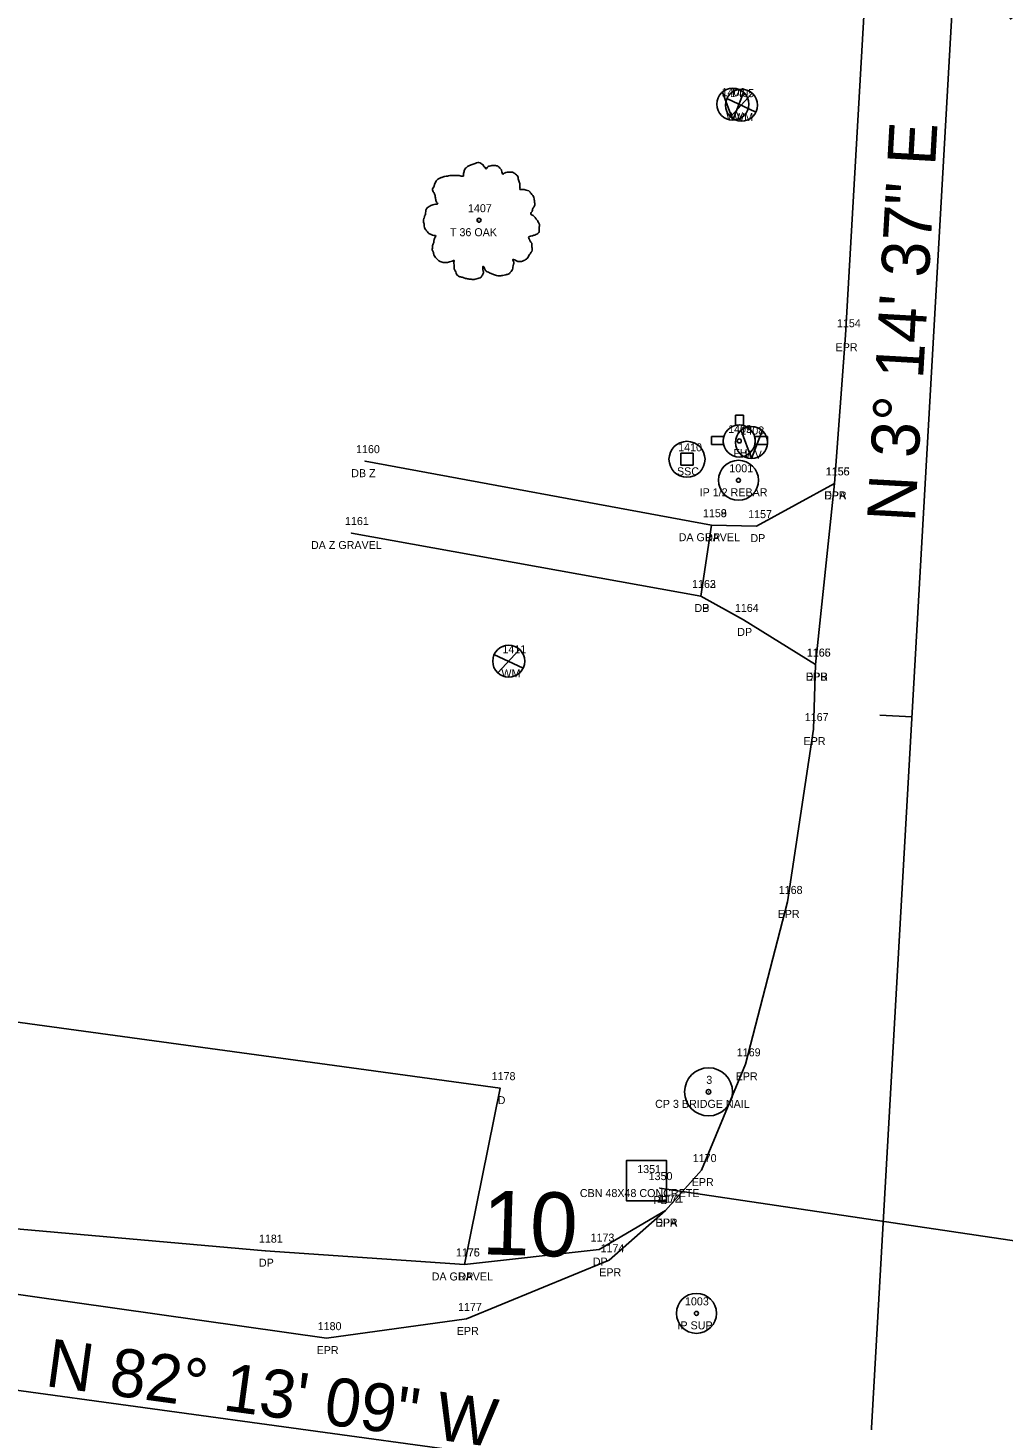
# Model space of a CAD drawing. Extents: x 1812340 to 1815011, y 1177659 to 1180159.
# Drawn here: x 1813558.8 to 1813680.6, y 1178765.1 to 1178939 of the extents above; entities that cross this region are included whole.
import ezdxf

# ---------------------------------------------------------------- set-up
doc = ezdxf.new("R2010")
doc.units = 0
for name, color, linetype in [('RD_EX_DR_Inlet', 7, 'Continuous'), ('RD_EX_DR_Inlet_txCode', 7, 'Continuous'), ('RD_EX_DR_Pipe', 7, 'Continuous'), ('RD_EX_DR_Pipe_txCode', 7, 'Continuous'), ('RD_EX_Driveway', 7, 'Continuous'), ('RD_EX_Driveway_txCode', 7, 'Continuous'), ('RD_EX_DV_Prop_txCode', 7, 'Continuous'), ('RD_EX_DV_PropPin', 7, 'Continuous'), ('RD_EX_Road', 7, 'Continuous'), ('RD_EX_Road_txCode', 7, 'Continuous'), ('RD_EX_UT', 7, 'Continuous'), ('RD_EX_UT_txCode', 7, 'Continuous'), ('RD_EX_VEG', 7, 'Continuous'), ('RD_EX_VEG_txCode', 7, 'Continuous'), ('RD_HC_CL', 7, 'Continuous'), ('RD_HC_Data', 7, 'Continuous'), ('RD_HC_Data_Tic', 7, 'Continuous'), ('RD_HC_TX_Sta50', 7, 'Continuous'), ('RD_HC_txCode', 7, 'Continuous'), ('RD_SMD_Locator', 7, 'Continuous')]:
    doc.layers.add(name, color=color, linetype=linetype)

msp = doc.modelspace()

# ---------------------------------------------------------------- linework, layer by layer
at = {"layer": 'RD_EX_DR_Inlet'}
msp.add_line((1813638.56, 1178792.49), (1813638.56, 1178797.49), dxfattribs=at)
msp.add_lwpolyline([(1813638.56, 1178792.49), (1813638.56, 1178797.49), (1813633.56, 1178797.49), (1813633.56, 1178792.49)], close=True, dxfattribs=at)
at = {"layer": 'RD_EX_DR_Pipe'}
msp.add_line((1813690.77, 1178786.15), (1813637.71, 1178794.06), dxfattribs=at)
at = {"layer": 'RD_EX_Driveway'}
for p, q in [((1813644.18, 1178876.9), (1813600.91, 1178884.9)), ((1813599.2, 1178875.92), (1813642.83, 1178868.05))]:
    msp.add_line(p, q, dxfattribs=at)
for points in [[(1813659.53, 1178882.12), (1813649.82, 1178876.78), (1813644.18, 1178876.9), (1813642.83, 1178868.05), (1813648.18, 1178865.06), (1813657.19, 1178859.48)], [(1813613.34, 1178784.52), (1813617.78, 1178806.55), (1813543.17, 1178816.74), (1813525.31, 1178791.79)], [(1813638.42, 1178791.25), (1813630.13, 1178786.38), (1813613.34, 1178784.52), (1813588.43, 1178786.24), (1813525.31, 1178791.79), (1813522.62, 1178785.74)]]:
    msp.add_lwpolyline(points, dxfattribs=at)
at = {"layer": 'RD_EX_DV_PropPin'}
for centre, radius in [((1813647.55, 1178882.51), 2.5), ((1813647.55, 1178882.51), 0.25), ((1813642.3, 1178778.41), 2.5), ((1813642.3, 1178778.41), 0.25)]:
    msp.add_circle(centre, radius, dxfattribs=at)
at = {"layer": 'RD_EX_Road'}
msp.add_lwpolyline([(1813668.47, 1179045.78), (1813666.19, 1178996.77), (1813663.63, 1178947.81), (1813660.91, 1178900.64), (1813659.53, 1178882.12), (1813657.19, 1178859.48), (1813656.91, 1178851.42), (1813653.67, 1178829.82), (1813648.43, 1178809.53), (1813642.94, 1178796.31), (1813638.42, 1178791.25), (1813631.39, 1178785.04), (1813613.59, 1178777.71), (1813596.09, 1178775.31), (1813522.62, 1178785.74), (1813518.21, 1178785.19), (1813499.47, 1178787.87), (1813450.56, 1178796.06), (1813414.35, 1178802.92), (1813398.64, 1178806.42), (1813355.44, 1178817.13)], dxfattribs=at)
at = {"layer": 'RD_EX_UT'}
for p, q in [((1813646.85, 1178927.52), (1813645.55, 1178931)), ((1813646.56, 1178927.93), (1813649.23, 1178930.83)), ((1813646.85, 1178927.52), (1813648.18, 1178930.96)), ((1813646.08, 1178930.23), (1813649.71, 1178928.51)), ((1813647.19, 1178890.64), (1813647.19, 1178889.37)), ((1813648.19, 1178890.64), (1813647.19, 1178890.64)), ((1813648.19, 1178889.34), (1813648.19, 1178890.64)), ((1813649.18, 1178885.24), (1813647.88, 1178888.72)), ((1813649.18, 1178885.24), (1813650.5, 1178888.68)), ((1813645.73, 1178887.99), (1813644.17, 1178887.99)), ((1813644.17, 1178887.99), (1813644.17, 1178886.99)), ((1813644.17, 1178886.99), (1813645.69, 1178886.99)), ((1813651.17, 1178887.99), (1813649.56, 1178887.99)), ((1813649.6, 1178886.99), (1813651.17, 1178886.99)), ((1813651.17, 1178886.99), (1813651.17, 1178887.99)), ((1813641.87, 1178885.88), (1813640.37, 1178885.88)), ((1813640.37, 1178885.88), (1813640.37, 1178884.38)), ((1813641.87, 1178884.38), (1813641.87, 1178885.88)), ((1813640.37, 1178884.38), (1813641.87, 1178884.38)), ((1813617.5, 1178858.44), (1813620.16, 1178861.34)), ((1813617.01, 1178860.74), (1813620.65, 1178859.02))]:
    msp.add_line(p, q, dxfattribs=at)
for centre, radius in [((1813646.85, 1178929.51), 2), ((1813647.92, 1178929.39), 2), ((1813647.65, 1178887.42), 2), ((1813649.18, 1178887.23), 2), ((1813641.12, 1178885.13), 2.25), ((1813647.65, 1178887.42), 0.25), ((1813618.85, 1178859.9), 2)]:
    msp.add_circle(centre, radius, dxfattribs=at)
for start, end in [(74.2455, 103.2128), (163.3387, 192.315), (347.685, 16.6613)]:
    msp.add_arc((1813647.65, 1178887.42), 2, start, end, dxfattribs=at)
at = {"layer": 'RD_EX_VEG'}
for centre, radius in [((1813615.14, 1178915.01), 0.25), ((1813615.13, 1178914.99), 0.0001)]:
    msp.add_circle(centre, radius, dxfattribs=at)
for points in [[(1813615.28, 1178922.18), (1813614.98, 1178922.21), (1813614.65, 1178922.11), (1813614.4, 1178922.01), (1813614.18, 1178921.93), (1813613.95, 1178921.83), (1813613.65, 1178921.66), (1813613.43, 1178921.46), (1813613.3, 1178921.21), (1813613.25, 1178920.98), (1813613.2, 1178920.71), (1813613.2, 1178920.53), (1813613.08, 1178920.51), (1813612.93, 1178920.53), (1813612.68, 1178920.61), (1813612.43, 1178920.61), (1813612.18, 1178920.61), (1813611.83, 1178920.58), (1813611.48, 1178920.58), (1813611.2, 1178920.53), (1813610.88, 1178920.48), (1813610.5, 1178920.36), (1813610.15, 1178920.23), (1813609.85, 1178919.98), (1813609.6, 1178919.51), (1813609.48, 1178919.16), (1813609.33, 1178918.91), (1813609.48, 1178918.46), (1813609.65, 1178918.11), (1813609.68, 1178917.91), (1813609.75, 1178917.48), (1813609.85, 1178917.26), (1813609.98, 1178917.06), (1813609.9, 1178917.03), (1813609.53, 1178916.98), (1813609.23, 1178916.88), (1813608.8, 1178916.66), (1813608.58, 1178916.43), (1813608.48, 1178916.11), (1813608.45, 1178915.76), (1813608.35, 1178915.56), (1813608.28, 1178915.28), (1813608.25, 1178915.21), (1813608.2, 1178914.88), (1813608.3, 1178914.43), (1813608.33, 1178914.08), (1813608.45, 1178913.86), (1813608.6, 1178913.68), (1813608.78, 1178913.43), (1813609.18, 1178913.21), (1813609.5, 1178913.11), (1813609.7, 1178913.09), (1813609.53, 1178912.59), (1813609.48, 1178912.24), (1813609.35, 1178911.84), (1813609.35, 1178911.76), (1813609.3, 1178911.29), (1813609.45, 1178910.96), (1813609.53, 1178910.59), (1813609.7, 1178910.36), (1813609.98, 1178910.06), (1813610.3, 1178909.84), (1813610.8, 1178909.71), (1813611.2, 1178909.74), (1813611.78, 1178909.91), (1813612.03, 1178909.99), (1813612, 1178909.81), (1813612.03, 1178909.44), (1813612.03, 1178909.01), (1813612.18, 1178908.69), (1813612.28, 1178908.41), (1813612.43, 1178908.16), (1813612.75, 1178907.94), (1813613.15, 1178907.86), (1813613.58, 1178907.71), (1813614.03, 1178907.64), (1813614.53, 1178907.61), (1813615.13, 1178907.76), (1813615.4, 1178907.89), (1813615.5, 1178908.06), (1813615.7, 1178908.44), (1813615.65, 1178908.66), (1813615.68, 1178909.26), (1813615.78, 1178909.09), (1813615.95, 1178908.74), (1813616.45, 1178908.44), (1813616.85, 1178908.26), (1813617.33, 1178908.11), (1813617.63, 1178908.04), (1813618.1, 1178908.11), (1813618.48, 1178908.19), (1813618.85, 1178908.31), (1813619.15, 1178908.59), (1813619.33, 1178908.86), (1813619.38, 1178909.14), (1813619.45, 1178909.51), (1813619.5, 1178909.69)], [(1813619.5, 1178909.69), (1813619.43, 1178909.86), (1813619.38, 1178910.11), (1813619.45, 1178910.09), (1813619.62, 1178910.04), (1813619.9, 1178909.91), (1813620.12, 1178909.84), (1813620.45, 1178909.86), (1813620.72, 1178909.96), (1813621.17, 1178910.24), (1813621.45, 1178910.71), (1813621.72, 1178911.11), (1813621.8, 1178911.44), (1813621.75, 1178911.66), (1813621.72, 1178912.16), (1813621.52, 1178912.41), (1813621.47, 1178912.54), (1813621.37, 1178912.94), (1813621.45, 1178912.99), (1813621.72, 1178913.04), (1813622.1, 1178913.16), (1813622.37, 1178913.28), (1813622.6, 1178913.46), (1813622.67, 1178913.68), (1813622.65, 1178914.08), (1813622.7, 1178914.48), (1813622.62, 1178914.63), (1813622.52, 1178914.78), (1813622.45, 1178914.98), (1813622.3, 1178915.13), (1813622.2, 1178915.28), (1813622.1, 1178915.38), (1813621.97, 1178915.53), (1813621.8, 1178915.66), (1813621.65, 1178915.71), (1813621.6, 1178915.86), (1813621.75, 1178916.06), (1813621.8, 1178916.16), (1813621.82, 1178916.38), (1813622.05, 1178916.73), (1813622.1, 1178917.13), (1813622.05, 1178917.56), (1813622, 1178917.83), (1813621.85, 1178918.11), (1813621.65, 1178918.36), (1813621.52, 1178918.53), (1813621.35, 1178918.66), (1813621.02, 1178918.78), (1813620.77, 1178918.83), (1813620.42, 1178918.83), (1813620.22, 1178918.88), (1813620.25, 1178918.93), (1813620.25, 1178919.08), (1813620.25, 1178919.36), (1813620.17, 1178919.81), (1813620.02, 1178920.31), (1813620.02, 1178920.33), (1813619.92, 1178920.58), (1813619.7, 1178920.78), (1813619.52, 1178920.88), (1813619.33, 1178921.01), (1813619.08, 1178921.03), (1813618.78, 1178921.03), (1813618.5, 1178920.98), (1813618.3, 1178920.88), (1813618.13, 1178920.76), (1813618.05, 1178920.91), (1813617.95, 1178921.21), (1813617.9, 1178921.36), (1813617.75, 1178921.53), (1813617.53, 1178921.73), (1813617.08, 1178921.86), (1813616.45, 1178921.78), (1813616.15, 1178921.58), (1813616, 1178921.41), (1813615.95, 1178921.53), (1813615.75, 1178921.73), (1813615.65, 1178921.91), (1813615.48, 1178922.03), (1813615.33, 1178922.13), (1813615.23, 1178922.18)]]:
    msp.add_spline(points, degree=3, dxfattribs=at)
at = {"layer": 'RD_HC_CL'}
for p, q in [((1813663.56, 1178753.12), (1813680.53, 1179052.64)), ((1813641.28, 1178757.34), (1813538.22, 1178771.42))]:
    msp.add_line(p, q, dxfattribs=at)
at = {"layer": 'RD_HC_Data'}
for radius in [3, 0.282]:
    msp.add_circle((1813643.81, 1178806.09), radius, dxfattribs=at)
at = {"layer": 'RD_HC_Data_Tic'}
msp.add_line((1813669.21, 1178852.96), (1813665.22, 1178853.18), dxfattribs=at)
at = {"layer": 'RD_SMD_Locator'}
for centre in [(1813660.91, 1178900.64), (1813600.91, 1178884.9), (1813659.53, 1178882.12), (1813659.53, 1178882.12), (1813644.18, 1178876.9), (1813644.18, 1178876.9), (1813649.82, 1178876.78), (1813599.2, 1178875.92), (1813642.83, 1178868.05), (1813642.83, 1178868.05), (1813648.18, 1178865.06), (1813657.19, 1178859.48), (1813657.19, 1178859.48), (1813656.91, 1178851.42), (1813653.67, 1178829.82), (1813648.43, 1178809.53), (1813617.78, 1178806.55), (1813643.81, 1178806.09), (1813642.94, 1178796.31), (1813637.71, 1178794.06), (1813638.42, 1178791.25), (1813638.42, 1178791.25), (1813588.43, 1178786.24), (1813630.13, 1178786.38), (1813613.34, 1178784.52), (1813613.34, 1178784.52), (1813631.39, 1178785.04), (1813613.59, 1178777.71), (1813596.09, 1178775.31)]:
    msp.add_circle(centre, 0.001, dxfattribs=at)

# ---------------------------------------------------------------- texts
at = {"layer": 'RD_EX_DR_Inlet_txCode'}
for s, p in [('1351', (1813634.9, 1178795.94)), ('CBN 48X48 CONCRETE', (1813627.74, 1178792.94))]:
    msp.add_text(s, height=1, dxfattribs=at).set_placement(p)
at = {"layer": 'RD_EX_DR_Pipe_txCode'}
for s, p in [('1350', (1813636.33, 1178795.06)), ('PB', (1813636.93, 1178792.06))]:
    msp.add_text(s, height=1, dxfattribs=at).set_placement(p)
at = {"layer": 'RD_EX_Driveway_txCode'}
for s, p in [('1160', (1813599.78, 1178885.9)), ('DB Z', (1813599.18, 1178882.9)), ('1156', (1813658.44, 1178883.12)), ('DPA', (1813658.26, 1178880.12)), ('1158', (1813643.11, 1178877.9)), ('1159', (1813643.11, 1178877.9)), ('1157', (1813648.76, 1178877.78)), ('1161', (1813598.4, 1178876.92)), ('DA Z GRAVEL', (1813594.15, 1178873.92)), ('DA GRAVEL', (1813640.08, 1178874.9)), ('DP', (1813643.4, 1178874.9)), ('DP', (1813649.04, 1178874.78)), ('1162', (1813641.75, 1178869.05)), ('1163', (1813641.75, 1178869.05)), ('DB', (1813642.05, 1178866.05)), ('DP', (1813642.05, 1178866.05)), ('1164', (1813647.1, 1178866.06)), ('DP', (1813647.4, 1178863.06)), ('1165', (1813656.1, 1178860.48)), ('DPB', (1813655.94, 1178857.48)), ('1178', (1813616.72, 1178807.55)), ('D', (1813617.47, 1178804.55)), ('1172', (1813637.36, 1178792.25)), ('DPA', (1813637.16, 1178789.25)), ('1181', (1813587.65, 1178787.24)), ('1173', (1813629.07, 1178787.38)), ('1176', (1813612.25, 1178785.52)), ('1175', (1813612.27, 1178785.52)), ('DP', (1813587.65, 1178784.24)), ('DP', (1813629.35, 1178784.38)), ('DA GRAVEL', (1813609.23, 1178782.52)), ('DP', (1813612.56, 1178782.52))]:
    msp.add_text(s, height=1, dxfattribs=at).set_placement(p)
at = {"layer": 'RD_EX_DV_Prop_txCode'}
for s, p in [('1001', (1813646.41, 1178883.51)), ('IP 1/2 REBAR', (1813642.7, 1178880.51)), ('1003', (1813640.87, 1178779.41)), ('IP SUP', (1813639.93, 1178776.41))]:
    msp.add_text(s, height=1, dxfattribs=at).set_placement(p)
at = {"layer": 'RD_EX_Road_txCode'}
for s, p in [('1154', (1813659.85, 1178901.64)), ('EPR', (1813659.68, 1178898.64)), ('1155', (1813658.47, 1178883.12)), ('EPR', (1813658.3, 1178880.12)), ('1166', (1813656.08, 1178860.48)), ('EPR', (1813655.96, 1178857.48)), ('1167', (1813655.83, 1178852.42)), ('EPR', (1813655.68, 1178849.42)), ('1168', (1813652.58, 1178830.82)), ('EPR', (1813652.44, 1178827.82)), ('1169', (1813647.34, 1178810.53)), ('EPR', (1813647.2, 1178807.53)), ('1170', (1813641.84, 1178797.31)), ('EPR', (1813641.71, 1178794.31)), ('1171', (1813637.65, 1178792.25)), ('EPR', (1813637.2, 1178789.25)), ('1174', (1813630.32, 1178786.04)), ('EPR', (1813630.16, 1178783.04)), ('1177', (1813612.52, 1178778.71)), ('1180', (1813594.99, 1178776.31)), ('EPR', (1813612.36, 1178775.71)), ('EPR', (1813594.86, 1178773.31))]:
    msp.add_text(s, height=1, dxfattribs=at).set_placement(p)
at = {"layer": 'RD_EX_UT_txCode'}
for s, p in [('1406', (1813645.44, 1178930.51)), ('1405', (1813646.53, 1178930.39)), ('WV', (1813646, 1178927.51)), ('WM', (1813647.01, 1178927.39)), ('1409', (1813646.26, 1178888.42)), ('1408', (1813647.79, 1178888.23)), ('1410', (1813640.02, 1178886.13)), ('FH', (1813646.91, 1178885.42)), ('WV', (1813648.32, 1178885.23)), ('SSC', (1813639.87, 1178883.13)), ('1411', (1813618.07, 1178860.9)), ('WM', (1813617.94, 1178857.9))]:
    msp.add_text(s, height=1, dxfattribs=at).set_placement(p)
at = {"layer": 'RD_EX_VEG_txCode'}
for s, p in [('1407', (1813613.76, 1178916.01)), ('T 36 OAK', (1813611.51, 1178913.01))]:
    msp.add_text(s, height=1, dxfattribs=at).set_placement(p)
at = {"layer": 'RD_HC_Data'}
for s, rotation, p in [('S 36%%d 04\' 29" E', 306.0747, (1813658.75, 1178971.31)), ('N 3%%d 14\' 37" E', 86.7565, (1813669.59, 1178877.2)), ('N 82%%d 13\' 09" W', 352.2191, (1813560.83, 1178769.34))]:
    msp.add_text(s, height=6, rotation=rotation, dxfattribs=at).set_placement(p)
at = {"layer": 'RD_HC_TX_Sta50'}
msp.add_text('10', height=8, rotation=358.2694, dxfattribs=at).set_placement((1813615.46, 1178785.8))
at = {"layer": 'RD_HC_txCode'}
for s, p in [('3', (1813643.53, 1178807.09)), ('CP 3 BRIDGE NAIL', (1813637.14, 1178804.09))]:
    msp.add_text(s, height=1, dxfattribs=at).set_placement(p)

doc.saveas('drawing.dxf')
